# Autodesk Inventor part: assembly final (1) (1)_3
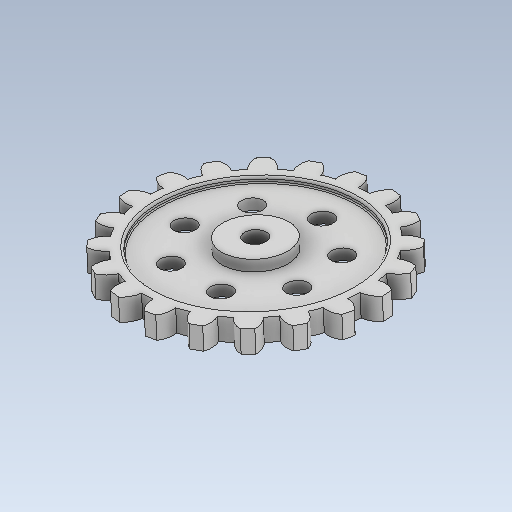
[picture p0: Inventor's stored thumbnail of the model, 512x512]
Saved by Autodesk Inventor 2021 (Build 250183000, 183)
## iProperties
Created: 2021-07
Part Number: assembly final (1) (1)_3
Material: Generic
Document SubType Name: Modeling
Designer: TARUN
Density: 1 g/cm^3
Appearance: Default
Author: TARUN
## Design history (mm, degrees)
feature "Base1"
body "Solid1"
